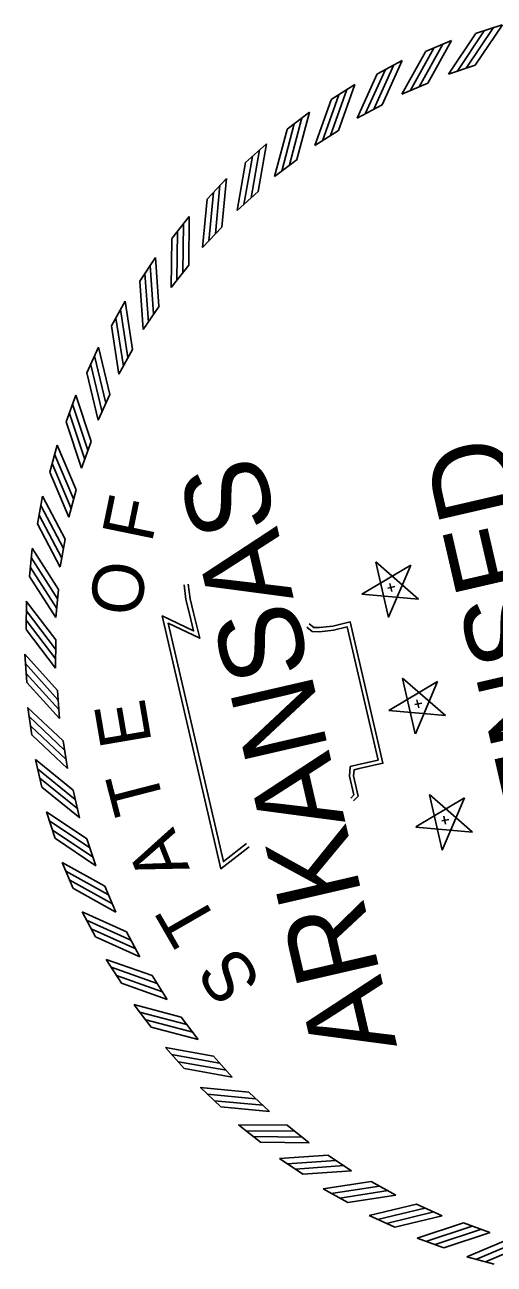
# Model space of a CAD drawing. Extents: x 634644 to 1109508, y 286699 to 700437.
# Drawn here: x 1108182.7 to 1108220.4, y 700314.5 to 700414.1 of the extents above; entities that cross this region are included whole.
import ezdxf

# ---------------------------------------------------------------- set-up
doc = ezdxf.new("R2010")
doc.units = 0
doc.layers.add('R_Border', color=7, linetype='Continuous')

msp = doc.modelspace()

# ---------------------------------------------------------------- linework, layer by layer
at = {"layer": 'R_Border'}
for p, q in [((1108218.946, 700413.361), (1108221.094, 700414.07)), ((1108214.935, 700411.915), (1108217.017, 700412.799)), ((1108211.056, 700410.144), (1108213.058, 700411.197)), ((1108216.769, 700410.108), (1108218.922, 700410.818)), ((1108207.337, 700408.058), (1108209.246, 700409.273)), ((1108213.034, 700408.494), (1108215.121, 700409.38)), ((1108203.803, 700405.672), (1108205.605, 700407.04)), ((1108209.444, 700406.577), (1108211.451, 700407.632)), ((1108206.026, 700404.37), (1108207.938, 700405.588)), ((1108200.479, 700403.003), (1108202.161, 700404.515)), ((1108202.801, 700401.889), (1108204.606, 700403.26)), ((1108197.386, 700400.068), (1108198.937, 700401.714)), ((1108199.792, 700399.149), (1108201.478, 700400.665)), ((1108194.546, 700396.888), (1108195.956, 700398.656)), ((1108197.019, 700396.171), (1108198.575, 700397.821)), ((1108191.978, 700393.484), (1108193.238, 700395.363)), ((1108194.502, 700392.974), (1108195.916, 700394.746)), ((1108189.7, 700389.88), (1108190.8, 700391.856)), ((1108192.258, 700389.58), (1108193.521, 700391.463)), ((1108187.728, 700386.1), (1108188.661, 700388.16)), ((1108190.302, 700386.012), (1108191.404, 700387.993)), ((1108186.074, 700382.169), (1108186.834, 700384.3)), ((1108188.647, 700382.295), (1108189.582, 700384.36)), ((1108184.751, 700378.116), (1108185.332, 700380.302)), ((1108187.304, 700378.453), (1108188.066, 700380.589)), ((1108183.766, 700373.968), (1108184.165, 700376.194)), ((1108186.283, 700374.515), (1108186.866, 700376.706)), ((1108185.591, 700370.505), (1108185.991, 700372.736)), ((1108183.128, 700369.752), (1108183.342, 700372.004)), ((1108213.734, 700370.66), (1108209.818, 700368.312)), ((1108214.369, 700367.913), (1108210.925, 700370.912)), ((1108210.925, 700370.906), (1108211.948, 700366.456)), ((1108211.952, 700366.461), (1108213.74, 700370.662)), ((1108212.222, 700368.531), (1108212.07, 700369.192)), ((1108185.233, 700366.451), (1108185.447, 700368.709)), ((1108209.824, 700368.311), (1108214.372, 700367.908)), ((1108211.911, 700368.797), (1108212.469, 700368.926)), ((1108182.84, 700365.498), (1108182.867, 700367.759)), ((1108185.21, 700362.382), (1108185.237, 700364.65)), ((1108182.905, 700361.234), (1108182.745, 700363.491)), ((1108215.893, 700361.312), (1108211.976, 700358.964)), ((1108216.527, 700358.564), (1108213.083, 700361.563)), ((1108213.084, 700361.558), (1108214.107, 700357.107)), ((1108214.11, 700357.112), (1108215.898, 700361.314)), ((1108185.524, 700358.326), (1108185.364, 700360.587)), ((1108183.321, 700356.991), (1108182.975, 700359.226)), ((1108214.069, 700359.448), (1108214.627, 700359.577)), ((1108214.381, 700359.182), (1108214.228, 700359.844)), ((1108211.982, 700358.962), (1108216.53, 700358.56)), ((1108186.171, 700354.308), (1108185.825, 700356.549)), ((1108184.109, 700352.824), (1108183.6, 700355.028)), ((1108187.148, 700350.358), (1108186.638, 700352.567)), ((1108218.685, 700349.216), (1108215.242, 700352.215)), ((1108215.242, 700352.209), (1108216.265, 700347.759)), ((1108218.051, 700351.963), (1108214.135, 700349.615)), ((1108216.268, 700347.763), (1108218.056, 700351.965)), ((1108185.195, 700348.679), (1108184.486, 700350.827)), ((1108216.227, 700350.1), (1108216.785, 700350.229)), ((1108216.539, 700349.834), (1108216.386, 700350.495)), ((1108214.14, 700349.613), (1108218.689, 700349.211)), ((1108188.448, 700346.502), (1108187.738, 700348.655)), ((1108186.64, 700344.668), (1108185.757, 700346.75)), ((1108190.062, 700342.767), (1108189.176, 700344.854)), ((1108188.412, 700340.79), (1108187.359, 700342.792)), ((1108191.979, 700339.178), (1108190.924, 700341.184)), ((1108190.498, 700337.071), (1108189.283, 700338.979)), ((1108194.186, 700335.759), (1108192.968, 700337.672)), ((1108192.884, 700333.537), (1108191.516, 700335.338)), ((1108196.667, 700332.534), (1108195.296, 700334.34)), ((1108195.553, 700330.212), (1108194.041, 700331.894)), ((1108199.406, 700329.525), (1108197.891, 700331.212)), ((1108198.488, 700327.119), (1108196.842, 700328.671)), ((1108202.385, 700326.753), (1108200.735, 700328.308)), ((1108201.668, 700324.279), (1108199.9, 700325.689)), ((1108205.582, 700324.236), (1108203.81, 700325.65)), ((1108205.072, 700321.711), (1108203.193, 700322.971)), ((1108208.976, 700321.991), (1108207.093, 700323.254)), ((1108208.676, 700319.433), (1108206.7, 700320.534)), ((1108212.544, 700320.035), (1108210.563, 700321.138)), ((1108212.456, 700317.461), (1108210.396, 700318.394)), ((1108216.261, 700318.38), (1108214.196, 700319.315)), ((1108220.102, 700317.037), (1108217.967, 700317.799)), ((1108216.386, 700315.807), (1108214.256, 700316.567)), ((1108220.44, 700314.484), (1108218.254, 700315.065))]:
    msp.add_line(p, q, dxfattribs=at)
for points in [[(1108218.919, 700410.819), (1108221.095, 700414.072)], [(1108216.767, 700410.105), (1108218.944, 700413.358)], [(1108217.461, 700410.327), (1108219.637, 700413.579)], [(1108218.201, 700410.589), (1108220.378, 700413.842)], [(1108213.705, 700408.769), (1108215.605, 700412.191)], [(1108214.421, 700409.092), (1108216.322, 700412.514)], [(1108215.118, 700409.38), (1108217.018, 700412.802)], [(1108211.448, 700407.632), (1108213.059, 700411.199)], [(1108213.032, 700408.491), (1108214.932, 700411.912)], [(1108209.443, 700406.574), (1108211.054, 700410.141)], [(1108210.09, 700406.907), (1108211.702, 700410.473)], [(1108210.778, 700407.288), (1108212.389, 700410.855)], [(1108207.935, 700405.587), (1108209.246, 700409.275)], [(1108206.025, 700404.367), (1108207.336, 700408.055)], [(1108206.642, 700404.752), (1108207.954, 700408.44)], [(1108207.296, 700405.189), (1108208.607, 700408.876)], [(1108204.603, 700403.26), (1108205.606, 700407.043)], [(1108203.384, 700402.32), (1108204.386, 700406.104)], [(1108203.999, 700402.809), (1108205.001, 700406.593)], [(1108202.8, 700401.885), (1108203.802, 700405.669)], [(1108200.91, 700400.166), (1108201.596, 700404.019)], [(1108201.475, 700400.664), (1108202.161, 700404.518)], [(1108199.791, 700399.146), (1108200.478, 700402.999)], [(1108200.337, 700399.628), (1108201.024, 700403.481)], [(1108198.05, 700397.276), (1108198.416, 700401.173)], [(1108198.572, 700397.82), (1108198.938, 700401.717)], [(1108197.019, 700396.168), (1108197.385, 700400.064)], [(1108197.523, 700396.693), (1108197.889, 700400.589)], [(1108195.438, 700394.16), (1108195.481, 700398.074)], [(1108195.913, 700394.745), (1108195.956, 700398.659)], [(1108194.962, 700393.535), (1108195.004, 700397.449)], [(1108194.502, 700392.97), (1108194.545, 700396.884)], [(1108193.518, 700391.462), (1108193.237, 700395.365)], [(1108192.669, 700390.177), (1108192.389, 700394.081)], [(1108193.092, 700390.84), (1108192.812, 700394.743)], [(1108192.258, 700389.576), (1108191.978, 700393.48)], [(1108191.029, 700387.336), (1108190.427, 700391.204)], [(1108191.402, 700387.991), (1108190.8, 700391.859)], [(1108190.662, 700386.641), (1108190.06, 700390.509)], [(1108190.302, 700386.009), (1108189.7, 700389.876)], [(1108189.579, 700384.358), (1108188.66, 700388.163)], [(1108189.262, 700383.675), (1108188.343, 700387.479)], [(1108188.647, 700382.291), (1108187.728, 700386.096)], [(1108188.954, 700382.952), (1108188.035, 700386.756)], [(1108188.063, 700380.587), (1108186.833, 700384.302)], [(1108187.804, 700379.88), (1108186.573, 700383.595)], [(1108187.305, 700378.45), (1108186.075, 700382.166)], [(1108187.556, 700379.134), (1108186.326, 700382.849)], [(1108186.864, 700376.703), (1108185.331, 700380.305)], [(1108186.663, 700375.977), (1108185.131, 700379.578)], [(1108186.285, 700374.511), (1108184.752, 700378.113)], [(1108186.478, 700375.213), (1108184.945, 700378.814)], [(1108185.989, 700372.734), (1108184.164, 700376.196)], [(1108185.849, 700371.994), (1108184.024, 700375.456)], [(1108185.728, 700371.217), (1108183.903, 700374.679)], [(1108185.593, 700370.502), (1108183.768, 700373.964)], [(1108185.367, 700367.957), (1108183.262, 700371.256)], [(1108185.445, 700368.706), (1108183.34, 700372.006)], [(1108185.31, 700367.173), (1108183.205, 700370.472)], [(1108185.235, 700366.449), (1108183.13, 700369.748)], [(1108200.553, 700348.28), (1108198.688, 700346.834), (1108194.254, 700365.987), (1108196.79, 700364.776), (1108196.288, 700366.83), (1108196.011, 700367.96), (1108195.873, 700369.122)], [(1108200.755, 700348.019), (1108198.483, 700346.256), (1108193.778, 700366.58), (1108196.304, 700365.375), (1108195.967, 700366.751), (1108195.686, 700367.901), (1108195.545, 700369.083)], [(1108185.236, 700364.647), (1108182.866, 700367.762)], [(1108185.22, 700363.894), (1108182.85, 700367.008)], [(1108185.228, 700363.108), (1108182.858, 700366.222)], [(1108185.212, 700362.38), (1108182.842, 700365.494)], [(1108205.389, 700365.673), (1108205.835, 700365.326), (1108206.415, 700365.303), (1108207.539, 700365.437), (1108208.639, 700365.691), (1108211.11, 700354.988), (1108209.536, 700354.624), (1108208.876, 700354.472), (1108208.821, 700353.686), (1108209.165, 700352.198), (1108208.917, 700351.939)], [(1108205.591, 700365.934), (1108205.954, 700365.652), (1108206.402, 700365.635), (1108207.482, 700365.763), (1108208.887, 700366.087), (1108211.507, 700354.74), (1108209.61, 700354.303), (1108209.188, 700354.205), (1108209.154, 700353.713), (1108209.527, 700352.098), (1108209.155, 700351.711)], [(1108185.362, 700360.584), (1108182.743, 700363.493)], [(1108185.409, 700359.832), (1108182.789, 700362.74)], [(1108185.481, 700359.05), (1108182.862, 700361.958)], [(1108185.526, 700358.323), (1108182.907, 700361.231)], [(1108185.824, 700356.546), (1108182.973, 700359.228)], [(1108185.932, 700355.8), (1108183.082, 700358.482)], [(1108186.069, 700355.026), (1108183.219, 700357.709)], [(1108186.174, 700354.306), (1108183.324, 700356.988)], [(1108186.637, 700352.564), (1108183.598, 700355.03)], [(1108186.8, 700351.829), (1108183.761, 700354.294)], [(1108186.994, 700351.067), (1108183.954, 700353.533)], [(1108187.151, 700350.356), (1108184.112, 700352.822)], [(1108187.737, 700348.652), (1108184.484, 700350.829)], [(1108187.967, 700347.935), (1108184.714, 700350.111)], [(1108188.229, 700347.194), (1108184.977, 700349.37)], [(1108188.451, 700346.501), (1108185.198, 700348.677)], [(1108189.176, 700344.851), (1108185.754, 700346.751)], [(1108189.464, 700344.155), (1108186.042, 700346.055)], [(1108189.787, 700343.438), (1108186.365, 700345.339)], [(1108190.065, 700342.765), (1108186.644, 700344.666)], [(1108190.924, 700341.181), (1108187.357, 700342.793)], [(1108191.268, 700340.511), (1108187.701, 700342.123)], [(1108191.649, 700339.824), (1108188.082, 700341.435)], [(1108191.982, 700339.176), (1108188.415, 700340.788)], [(1108192.968, 700337.669), (1108189.281, 700338.98)], [(1108193.367, 700337.029), (1108189.68, 700338.34)], [(1108193.804, 700336.376), (1108190.116, 700337.687)], [(1108194.189, 700335.758), (1108190.501, 700337.069)], [(1108195.296, 700334.337), (1108191.513, 700335.339)], [(1108195.747, 700333.732), (1108191.963, 700334.735)], [(1108196.236, 700333.117), (1108192.452, 700334.119)], [(1108196.67, 700332.533), (1108192.887, 700333.536)], [(1108197.891, 700331.208), (1108194.038, 700331.895)], [(1108198.39, 700330.643), (1108194.537, 700331.33)], [(1108198.928, 700330.071), (1108195.075, 700330.757)], [(1108199.41, 700329.525), (1108195.557, 700330.211)], [(1108200.736, 700328.305), (1108196.839, 700328.671)], [(1108201.28, 700327.783), (1108197.383, 700328.149)], [(1108201.863, 700327.257), (1108197.966, 700327.623)], [(1108202.388, 700326.753), (1108198.492, 700327.118)], [(1108203.811, 700325.647), (1108199.897, 700325.69)], [(1108204.395, 700325.171), (1108200.482, 700325.214)], [(1108205.021, 700324.695), (1108201.107, 700324.738)], [(1108205.585, 700324.236), (1108201.672, 700324.279)], [(1108207.094, 700323.251), (1108203.191, 700322.971)], [(1108207.716, 700322.826), (1108203.813, 700322.545)], [(1108208.379, 700322.403), (1108204.475, 700322.122)], [(1108208.98, 700321.992), (1108205.076, 700321.711)], [(1108210.565, 700321.135), (1108206.697, 700320.533)], [(1108211.22, 700320.763), (1108207.352, 700320.161)], [(1108211.915, 700320.396), (1108208.047, 700319.794)], [(1108212.547, 700320.036), (1108208.68, 700319.434)], [(1108214.198, 700319.313), (1108210.393, 700318.394)], [(1108214.881, 700318.996), (1108211.077, 700318.076)], [(1108215.604, 700318.687), (1108211.8, 700317.768)], [(1108216.265, 700318.381), (1108212.46, 700317.461)], [(1108217.969, 700317.797), (1108214.254, 700316.566)], [(1108218.676, 700317.537), (1108214.961, 700316.307)], [(1108219.422, 700317.289), (1108215.707, 700316.059)], [(1108220.106, 700317.038), (1108216.39, 700315.808)], [(1108221.853, 700316.597), (1108218.251, 700315.064)], [(1108222.579, 700316.397), (1108218.978, 700314.864)], [(1108223.343, 700316.212), (1108219.742, 700314.679)]]:
    msp.add_lwpolyline(points, dxfattribs=at)

# ---------------------------------------------------------------- texts
for s, height, rotation, p in [('LICENSED', 6.7161, 103, (1108231.382, 700337.663)), ('ARKANSAS', 6.7161, 103, (1108212.65, 700332.026)), ('F', 4.115, 78.36282, (1108192.942, 700372.367)), ('O', 4.115, 84.2218, (1108192.076, 700366.475)), ('E', 4.115, 99.67203, (1108192.949, 700356.422)), ('T', 4.115, 104.47887, (1108194.012, 700351.263)), ('A', 4.115, 111.67877, (1108196.005, 700346.269)), ('T', 4.115, 119.90148, (1108198.4, 700341.694)), ('S', 4.115, 122.77256, (1108201.866, 700337.124))]:
    msp.add_text(s, height=height, rotation=rotation, dxfattribs=at).set_placement(p)

doc.saveas('drawing.dxf')
